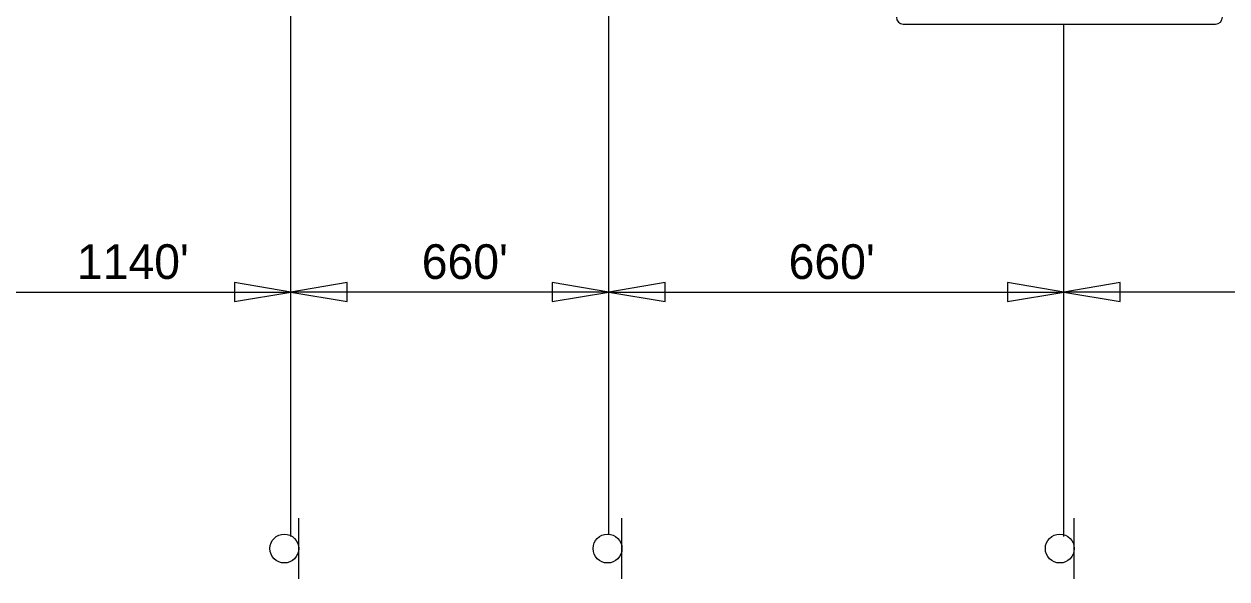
# Model space of a CAD drawing. Extents: x 2155255 to 2162649, y 140388 to 141878.
# Drawn here: x 2156712.5 to 2156920.8, y 141191.5 to 141287.5 of the extents above; entities that cross this region are included whole.
import ezdxf

# ---------------------------------------------------------------- set-up
doc = ezdxf.new("R2010")
doc.units = 0
for name, color, linetype in [('Default', 7, 'Continuous'), ('GSBWFILL', 7, 'Continuous'), ('PR_Dimensions1', 7, 'Continuous'), ('PR_Traffic_Control_Devices_Temp', 7, 'Continuous'), ('PR_Traffic_Temp_Txt', 7, 'Continuous')]:
    doc.layers.add(name, color=color, linetype=linetype)

# ---------------------------------------------------------------- blocks, each defined once
blk = doc.blocks.new('TCSIGN')
at = {"layer": 'Default'}
blk.add_line((5.26, 2.5), (-5.26, 2.5), dxfattribs=at)
blk.add_circle((0, 0), 2.5, dxfattribs=at)
blk = doc.blocks.new('Arrowhd')
at = {"layer": 'Default'}
blk.add_lwpolyline([(0.3175, -0.0529), (0.3175, 0.0529), (0, 0)], close=True, dxfattribs=at)

msp = doc.modelspace()

# ---------------------------------------------------------------- linework, layer by layer
at = {"layer": 'GSBWFILL'}
msp.add_lwpolyline([(2156864.73, 141287.55), (2156918.83, 141287.55)], dxfattribs=at)
for centre, start, end in [((2156864.73, 141288.72), 180, 270), ((2156918.83, 141288.72), 270, 0)]:
    msp.add_arc(centre, 1.18, start, end, dxfattribs=at)
at = {"layer": 'PR_Dimensions1'}
for p, q in [((2156758.68, 141198.84), (2156758.68, 141375.07)), ((2156813.73, 141199.25), (2156813.73, 141321.26)), ((2156892.55, 141198.84), (2156892.55, 141287.57)), ((2156698.96, 141241.15), (2156758.68, 141241.15)), ((2156813.73, 141241.15), (2156758.68, 141241.15)), ((2156813.73, 141241.15), (2156892.55, 141241.15)), ((2156988.21, 141241.15), (2156892.55, 141241.15))]:
    msp.add_line(p, q, dxfattribs=at)

# ---------------------------------------------------------------- block references
at = {"layer": 'PR_Dimensions1', "xscale": 30.761459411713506, "yscale": 30.761459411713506, "rotation": 180}
for p in [(2156758.68, 141241.15), (2156813.73, 141241.15), (2156892.55, 141241.15)]:
    msp.add_blockref('Arrowhd', p, dxfattribs=at)
at = {"layer": 'PR_Dimensions1', "xscale": 30.761459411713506, "yscale": 30.761459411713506}
for p in [(2156758.68, 141241.15), (2156813.73, 141241.15), (2156892.55, 141241.15)]:
    msp.add_blockref('Arrowhd', p, dxfattribs=at)
at = {"layer": 'PR_Traffic_Control_Devices_Temp', "rotation": -90.00000000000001}
for p in [(2156757.56, 141196.74), (2156813.53, 141196.74), (2156891.84, 141196.74)]:
    msp.add_blockref('TCSIGN', p, dxfattribs=at)

# ---------------------------------------------------------------- texts
at = {"layer": 'PR_Traffic_Temp_Txt'}
for s, p in [("1140'", (2156721.65, 141243.42)), ("660'", (2156781.36, 141243.42)), ("660'", (2156844.89, 141243.42))]:
    msp.add_text(s, height=6, rotation=360, dxfattribs=at).set_placement(p)

doc.saveas('drawing.dxf')
